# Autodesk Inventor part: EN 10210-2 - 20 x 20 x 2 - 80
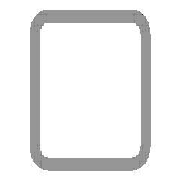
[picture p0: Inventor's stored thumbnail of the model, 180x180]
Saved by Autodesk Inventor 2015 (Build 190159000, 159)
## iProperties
Created: 2015-05
Part Number: EN 10210-2 - 20 x 20 x 2 - 80
Material: Steel, Mild
Description: Tube
Document SubType Name: Modeling
Standard: DIN
Designer: TREINA6
Standard Revision: 1997
Standards Organization: DIN
Language: en-US
Size Designation: 20 x 20 x 2
Categories: <MemberInstance><Categories><Category DisplayName="Structural Shapes" InternalName="089c4875-fa83-4c05-b084-43b9cc11f5ed" Mnemonic="GRDR"><CategoryParameter Dis
Stock Number: 20 x 20 x 2
Density: 7.85 g/cm^3
Appearance: Semi-Polished
IsCustomPart: 1
G_L: 80,000 mm
G_W: 20,000 mm
G_H: 20,000 mm
+B866034B-492E-4998-950C-155C7D90CDB3+CUTDETAIL1: Cut
_CCFamilyMember: 1
_CCFamilyDisplayName: DIN EN 10210-2 (Square) - Tube
_FrameMemberDoc: Frame Member File
_Version: 15.0.0
_GetPNFromCC: 1
Author: TREINA6
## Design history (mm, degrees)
node "Start plane"
node "End plane"
sketch "Sketch"
  geometry: L1 (-10, -7)-(-10, 7); L2 (-7, 10)-(7, 10); L3 (10, 7)-(10, -7); L4 (7, -10)-(-7, -10); L5 (-7, 8)-(7, 8); L6 (8, 7)-(8, -7); L7 (7, -8)-(-7, -8); L8 (-8, -7)-(-8, 7); L9 (0, 14.87)-(0, -14.87) reference; L10 (-14.87, 0)-(14.87, 0) reference; A1 r 3 centre (-7, -7) between (-10, -7) and (-7, -10); A2 r 3 centre (-7, 7) between (-7, 10) and (-10, 7); A3 r 3 centre (7, 7) between (10, 7) and (7, 10); A4 r 3 centre (7, -7) between (7, -10) and (10, -7); A5 r 1 centre (-7, 7) between (-7, 8) and (-8, 7); A6 r 1 centre (7, 7) between (8, 7) and (7, 8); A7 r 1 centre (7, -7) between (7, -8) and (8, -7); A8 r 1 centre (-7, -7) between (-8, -7) and (-7, -8)
  constraints: 16 end point, 16 point on circle, 8 centre point, 8 tangent, 4 parallel, 3 equal radius, 2 perpendicular, 7 other
  dimensions: "d7" = 3 radius of A1 (= G_IR); "d10" = 20 distance between parallel lines of L2 L4 (= G_H); "d11" = 20 distance between parallel lines of L1 L3 (= G_W); "d12" = 2 distance between parallel lines of L3 L6 (= G_T); "d15" = 10 distance between parallel lines of L2 L10 (= 0.5 x d10); "d16" = 10 distance between parallel lines of L9 L3 (= 0.5 x d11)
extrude "Body" new body sketch "Sketch" stored distance "d3" = 80 (= G_L); taper "d4" = 0 deg
node "Driven Length"
  sketch "Sketch3"
    geometry: L1 (0, 0)-(10, 0) reference
    constraints: 2 end point, 1 horizontal
  workplane "Work Plane3"
  sketch "Sketch4"
    geometry: L1 (-2, 0)-(12, 0) reference; L2 (-2, 80)-(12, 80) reference
    dimensions: "d18" = 80 distance between parallel lines of L1 L2 (derived)
workplane "Work Plane4"
split "Split1"
body "Solid1"
other parameters: "G_W" = 20 [user parameter; used in 1 equation term], "G_H" = 20 [user parameter; used in 1 equation term], "G_T" = 2 [user parameter; used in 1 equation term], "G_IR" = 3 [user parameter; used in 1 equation term], "G_L" = 80 (= d18) [user parameter; used in 1 equation term], "G_OFFSET_START" = 0 [user parameter; used in 1 equation term], "d13" = 0 (computed from G_OFFSET_START), "d17" = 90 deg
